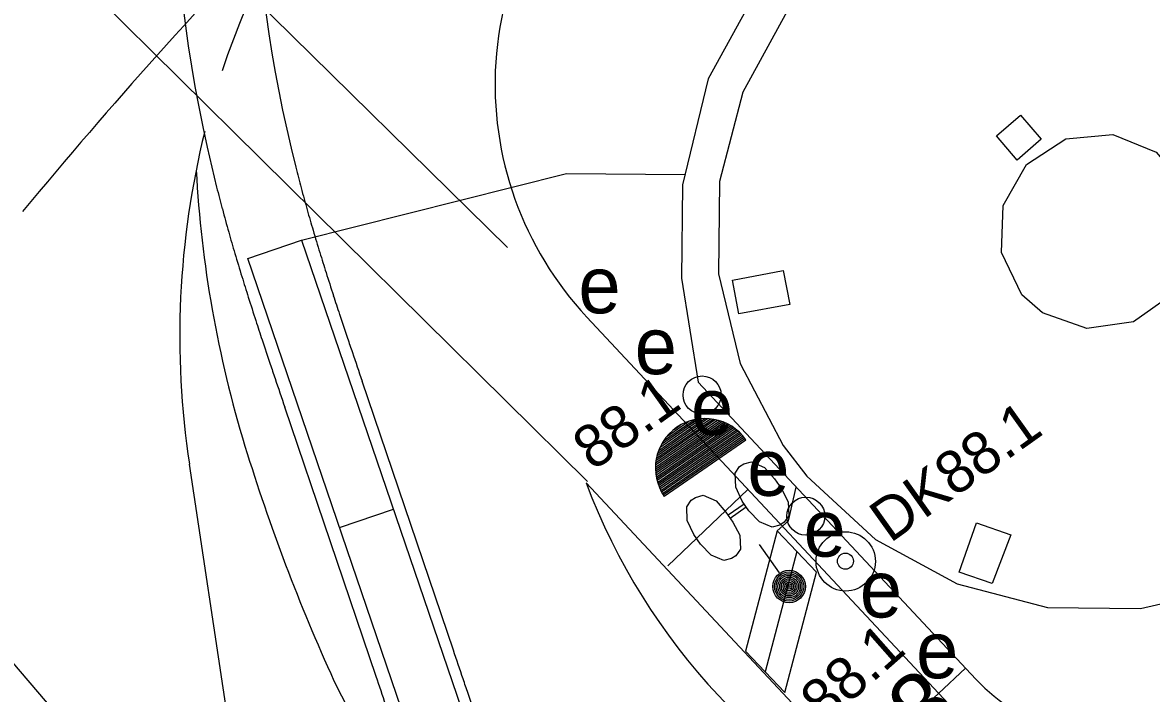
# Model space of a CAD drawing. Extents: x 81617 to 82144, y 454649 to 455150.
# Drawn here: x 81851.04 to 81870.9, y 454881.04 to 454892.85 of the extents above; entities that cross this region are included whole.
import ezdxf

# ---------------------------------------------------------------- set-up
doc = ezdxf.new("R2010")
doc.units = 0
for name, color, linetype in [('B-WE-OG-TOPOGRAFIE-G', 7, 'Continuous'), ('B-WE-VW-MARKERING-G', 7, 'Continuous'), ('N-OI-KL-VRI_KABEL_DETECTIE-G', 7, 'Continuous'), ('N-OI-KL-VRI_KABELGEUL-G', 7, 'Continuous'), ('N-OI-KL-VRI_LUS_DETECTIE-G', 7, 'Continuous'), ('N-OI-KL-VRI_LUS_DETECTIE-T18', 7, 'Continuous'), ('N-WE-VW-VRI_ARMATUUR-S', 7, 'Continuous'), ('N-WE-VW-VRI_ARMATUUR-T18', 7, 'Continuous'), ('N-WE-VW-VRI_MAST-S', 7, 'Continuous'), ('N-WE-VW-VRI_RICHTINGNUMMER-T25', 7, 'Continuous')]:
    doc.layers.add(name, color=color, linetype=linetype)

msp = doc.modelspace()

# ---------------------------------------------------------------- linework, layer by layer
at = {"layer": 'B-WE-OG-TOPOGRAFIE-G'}
for p, q in [((81864.496, 454893.051), (81863.715, 454891.626)), ((81863.715, 454891.626), (81863.305, 454890.053)), ((81863.305, 454890.053), (81863.289, 454888.428)), ((81863.289, 454888.428), (81863.67, 454886.848)), ((81863.67, 454886.848), (81864.423, 454885.408)), ((81858.624, 454881.804), (81857.017, 454886.542)), ((81857.265, 454881.343), (81855.658, 454886.081)), ((81864.423, 454885.408), (81864.842, 454884.865)), ((81864.842, 454884.865), (81866.049, 454883.756)), ((81866.049, 454883.756), (81867.488, 454882.971)), ((81867.488, 454882.971), (81869.073, 454882.556)), ((81870.712, 454882.537), (81872.307, 454882.913)), ((81869.073, 454882.556), (81870.712, 454882.537))]:
    msp.add_line(p, q, dxfattribs=at)
for points in [[(81868.177, 454890.856), (81868.602, 454891.22), (81868.967, 454890.796), (81868.543, 454890.431), (81868.177, 454890.856)], [(81871.645, 454889.635), (81871.649, 454888.803), (81871.269, 454888.063), (81870.591, 454887.582), (81869.768, 454887.467), (81868.985, 454887.745), (81868.625, 454888.058), (81868.267, 454888.805), (81868.296, 454889.633), (81868.704, 454890.354), (81869.398, 454890.805), (81870.223, 454890.883), (81870.99, 454890.571), (81871.527, 454889.94), (81871.645, 454889.635)], [(81864.54, 454887.889), (81863.647, 454887.723), (81863.534, 454888.32), (81864.428, 454888.489), (81864.54, 454887.889)], [(81860.972, 454887.667), (81868.18, 454879.955)], [(81868.1, 454882.981), (81867.522, 454883.181), (81867.824, 454884.044), (81868.428, 454883.833), (81868.1, 454882.981)]]:
    msp.add_lwpolyline(points, dxfattribs=at)
for centre, radius, start, end in [((81879.363, 454896.235), 25.685, 143.017, 194.1581), ((81879.363, 454896.235), 24.25, 143.017, 194.1581), ((81865.356, 454891.764), 6, 129.48, 223.0627), ((81880.133, 454896.43), 25.044, 194.1581, 195.0137), ((81880.133, 454896.43), 26.479, 194.1581, 195.0137), ((81884.113, 454897.497), 29.164, 195.0137, 195.8082), ((81884.113, 454897.497), 30.599, 195.0137, 195.8082), ((81886.57, 454898.193), 31.718, 195.8082, 196.4805), ((81886.57, 454898.193), 33.153, 195.8082, 196.4805), ((81893.108, 454900.127), 38.536, 196.4805, 197.0916), ((81893.108, 454900.127), 39.971, 196.4805, 197.0916), ((81897.375, 454901.439), 43, 197.0916, 197.5805), ((81897.375, 454901.439), 44.435, 197.0916, 197.5805), ((81910.142, 454905.484), 56.393, 197.5805, 198.0084), ((81910.142, 454905.484), 57.828, 197.58054, 198.00835), ((81919.199, 454908.428), 65.917, 198.00835, 198.31393), ((81954.8, 454920.212), 103.417, 198.31393, 198.55839), ((81919.199, 454908.428), 67.352, 198.00835, 198.31393), ((81974.55, 454926.842), 124.25, 198.55839, 198.68062), ((81954.8, 454920.212), 104.852, 198.31393, 198.55839), ((82329.795, 455046.952), 499.25, 198.68062, 198.74174), ((81974.55, 454926.842), 125.685, 198.55839, 198.68062), ((82329.795, 455046.952), 500.685, 198.68062, 198.74174), ((81384.425, 454720.912), 500.75, 18.68062, 18.74174), ((81384.425, 454720.912), 499.315, 18.68062, 18.74174), ((81739.67, 454841.022), 125.75, 18.55839, 18.68062), ((81759.42, 454847.652), 104.917, 18.31393, 18.55839)]:
    msp.add_arc(centre, radius, start, end, dxfattribs=at)
at = {"layer": 'B-WE-VW-MARKERING-G'}
for p, q in [((81859.578, 454888.893), (81851.77, 454896.571)), ((81860.984, 454884.776), (81850.084, 454895.546)), ((81854.993, 454878.378), (81853.979, 454885.079)), ((81862.398, 454883.291), (81863.803, 454884.632)), ((81856.964, 454874.469), (81850.333, 454882.22))]:
    msp.add_line(p, q, dxfattribs=at)
msp.add_lwpolyline([(81860.959, 454884.75), (81866.865, 454878.432)], dxfattribs=at)
for centre, radius, start, end in [((81920.451, 454832.229), 90, 131.17648, 140.46049), ((81868.809, 454887.325), 15, 125.8906, 161.8334), ((81868.809, 454887.325), 15, 166.075, 188.611), ((81874.556, 454891.359), 20.487, 183.0975, 196.9209), ((81887.583, 454895.402), 34.126, 197.0494, 204.4676), ((81871.56, 454888.74), 11.327, 200.6243, 245.5093), ((81921.727, 454913.877), 72.905, 206.56935, 209.07707)]:
    msp.add_arc(centre, radius, start, end, dxfattribs=at)
at = {"layer": 'N-OI-KL-VRI_KABEL_DETECTIE-G'}
for p, q in [((81855.953, 454889.021), (81860.613, 454890.196)), ((81864.319, 454883.908), (81864.517, 454884.083)), ((81864.836, 454878.895), (81867.16, 454881.046))]:
    msp.add_line(p, q, dxfattribs=at)
at = {"layer": 'N-OI-KL-VRI_KABELGEUL-G'}
for p, q in [((81860.613, 454890.196), (81862.698, 454890.176)), ((81864.517, 454884.083), (81864.656, 454884.676)), ((81867.16, 454881.046), (81867.635, 454881.49))]:
    msp.add_line(p, q, dxfattribs=at)
msp.add_lwpolyline([(81866.417, 454899.179), (81868.086, 454897.232), (81867.77, 454896.961), (81865.148, 454894.713), (81863.965, 454893.434), (81863.103, 454891.862), (81862.654, 454889.993), (81862.638, 454888.354), (81862.929, 454886.524), (81867.816, 454881.297)], dxfattribs=at)
msp.add_arc((81870.263, 454883.584), 3.35, 223.0627, 282.8439, dxfattribs=at)
at = {"layer": 'N-OI-KL-VRI_LUS_DETECTIE-G'}
for p, q in [((81856.621, 454883.966), (81857.567, 454884.289)), ((81864.319, 454883.908), (81863.763, 454881.786)), ((81865.009, 454883.181), (81864.319, 454883.908)), ((81864.664, 454883.545), (81864.109, 454881.424)), ((81864.454, 454881.062), (81865.009, 454883.181)), ((81863.763, 454881.786), (81864.454, 454881.062))]:
    msp.add_line(p, q, dxfattribs=at)
msp.add_lwpolyline([(81859.18, 454879.556), (81858.234, 454879.234), (81855.008, 454888.699), (81855.953, 454889.021)], close=True, dxfattribs=at)
at = {"layer": 'N-WE-VW-VRI_ARMATUUR-S'}
for p, q in [((81862.177, 454885.027), (81863.345, 454885.831)), ((81862.178, 454884.991), (81863.379, 454885.818)), ((81862.179, 454885.065), (81863.31, 454885.844)), ((81862.179, 454884.953), (81863.413, 454885.806)), ((81862.181, 454885.103), (81863.271, 454885.853)), ((81862.182, 454884.919), (81863.441, 454885.788)), ((81862.186, 454885.143), (81863.231, 454885.864)), ((81862.188, 454884.887), (81863.471, 454885.775)), ((81862.191, 454884.852), (81863.503, 454885.757)), ((81862.198, 454885.185), (81863.191, 454885.873)), ((81862.199, 454884.821), (81863.528, 454885.739)), ((81862.204, 454885.228), (81863.145, 454885.878)), ((81862.204, 454884.792), (81863.554, 454885.724)), ((81862.215, 454884.759), (81863.581, 454885.705)), ((81862.219, 454885.275), (81863.096, 454885.881)), ((81862.235, 454885.32), (81863.05, 454885.883)), ((81862.257, 454885.374), (81862.99, 454885.882)), ((81862.284, 454885.429), (81862.928, 454885.874)), ((81862.322, 454885.492), (81862.857, 454885.861)), ((81862.378, 454885.567), (81862.768, 454885.837)), ((81862.506, 454885.689), (81862.611, 454885.764)), ((81862.224, 454884.731), (81863.604, 454885.684)), ((81862.233, 454884.701), (81863.627, 454885.664)), ((81862.246, 454884.673), (81863.652, 454885.645)), ((81862.258, 454884.645), (81863.672, 454885.622)), ((81862.271, 454884.616), (81863.694, 454885.601)), ((81862.287, 454884.59), (81863.714, 454885.578)), ((81862.3, 454884.563), (81863.732, 454885.554)), ((81862.316, 454884.538), (81863.753, 454885.53)), ((81862.334, 454884.513), (81863.77, 454885.507)), ((81863.733, 454885.084), (81863.869, 454885.12)), ((81863.869, 454885.12), (81864.098, 454885.021)), ((81863.581, 454884.921), (81863.657, 454885.036)), ((81863.591, 454884.674), (81863.581, 454884.921)), ((81863.657, 454885.036), (81863.733, 454885.084)), ((81864.098, 454885.021), (81864.272, 454884.823)), ((81864.272, 454884.823), (81864.396, 454884.643)), ((81862.883, 454884.495), (81863.018, 454884.532)), ((81863.018, 454884.532), (81863.244, 454884.435)), ((81863.705, 454884.429), (81863.591, 454884.674)), ((81864.396, 454884.643), (81864.513, 454884.414)), ((81862.728, 454884.329), (81862.807, 454884.446)), ((81862.738, 454884.085), (81862.728, 454884.329)), ((81862.807, 454884.446), (81862.883, 454884.495)), ((81863.244, 454884.435), (81863.418, 454884.236)), ((81863.458, 454884.185), (81863.741, 454884.383)), ((81863.491, 454884.131), (81863.776, 454884.327)), ((81863.821, 454884.259), (81863.705, 454884.429)), ((81864.513, 454884.414), (81864.525, 454884.171)), ((81863.418, 454884.236), (81863.54, 454884.056)), ((81864.007, 454884.064), (81863.821, 454884.259)), ((81864.525, 454884.171), (81864.444, 454884.059)), ((81862.854, 454883.844), (81862.738, 454884.085)), ((81863.54, 454884.056), (81863.66, 454883.829)), ((81864.231, 454883.972), (81864.007, 454884.064)), ((81864.367, 454884.007), (81864.231, 454883.972)), ((81864.444, 454884.059), (81864.367, 454884.007)), ((81862.969, 454883.674), (81862.854, 454883.844)), ((81863.66, 454883.829), (81863.674, 454883.583)), ((81863.156, 454883.477), (81862.969, 454883.674)), ((81863.674, 454883.583), (81863.592, 454883.468)), ((81864.361, 454883.167), (81864.007, 454883.664)), ((81863.382, 454883.381), (81863.156, 454883.477)), ((81863.518, 454883.417), (81863.382, 454883.381)), ((81863.592, 454883.468), (81863.518, 454883.417))]:
    msp.add_line(p, q, dxfattribs=at)
for centre, radius in [((81865.525, 454883.368), 0.522), ((81865.52, 454883.372), 0.141), ((81864.53, 454882.926), 0.286), ((81864.53, 454882.926), 0.256), ((81864.53, 454882.926), 0.226), ((81864.53, 454882.926), 0.196), ((81864.53, 454882.926), 0.166), ((81864.53, 454882.926), 0.136), ((81864.53, 454882.926), 0.106), ((81864.53, 454882.926), 0.0765), ((81864.53, 454882.926), 0.0465), ((81864.53, 454882.926), 0.0165)]:
    msp.add_circle(centre, radius, dxfattribs=at)
msp.add_arc((81863.051, 454885.009), 0.873, 34.6317, 214.6317, dxfattribs=at)
at = {"layer": 'N-WE-VW-VRI_MAST-S'}
for centre in [(81862.999, 454886.296), (81864.824, 454884.164)]:
    msp.add_circle(centre, 0.335, dxfattribs=at)

# ---------------------------------------------------------------- texts
at = {"layer": 'B-WE-OG-TOPOGRAFIE-G'}
for p in [(81860.823, 454887.734), (81861.813, 454886.663), (81862.803, 454885.593), (81863.794, 454884.522), (81864.784, 454883.452), (81865.774, 454882.381), (81866.764, 454881.311)]:
    msp.add_text('e', height=1, dxfattribs=at).set_placement(p)
at = {"layer": 'N-OI-KL-VRI_LUS_DETECTIE-T18'}
msp.add_text('D88.1', height=0.75, rotation=41.4026, dxfattribs=at).set_placement((81864.608, 454880.003))
at = {"layer": 'N-WE-VW-VRI_ARMATUUR-T18'}
for s, p in [('88.1', (81861.079, 454884.949)), ('DK88.1', (81866.306, 454883.68))]:
    msp.add_text(s, height=0.75, rotation=35.4794, dxfattribs=at).set_placement(p)
at = {"layer": 'N-WE-VW-VRI_RICHTINGNUMMER-T25'}
msp.add_text('88', height=1.2, rotation=40, dxfattribs=at).set_placement((81866.238, 454879.502))

doc.saveas('drawing.dxf')
